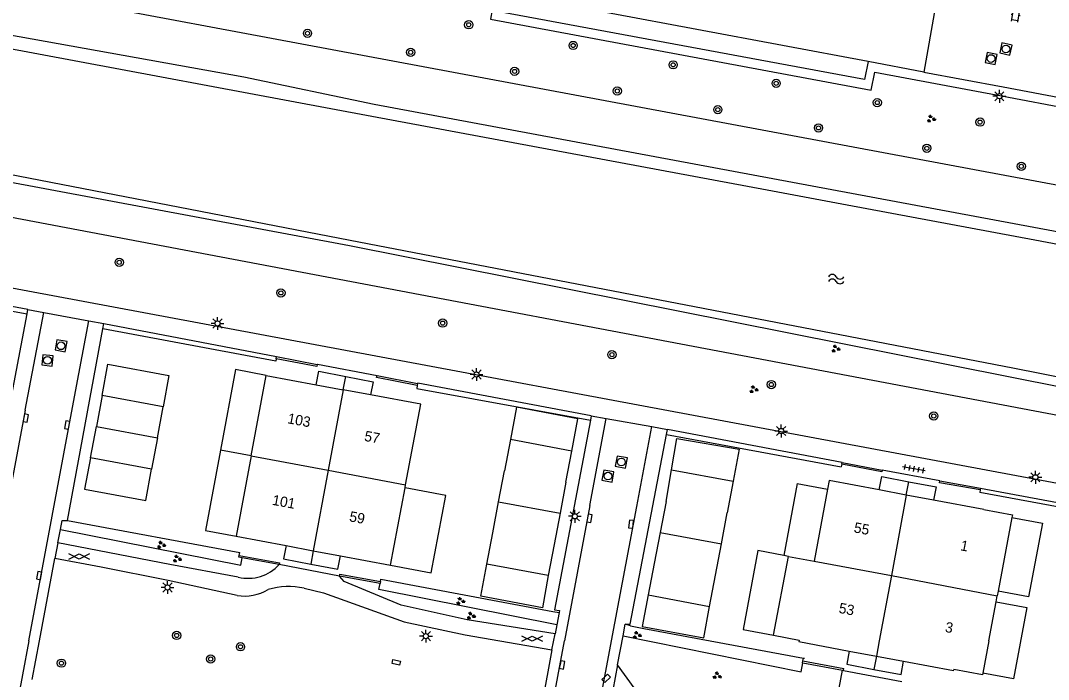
# Model space of a CAD drawing. Extents: x 124000 to 128010, y 398999 to 403000.
# Drawn here: x 126835.9 to 126935.6, y 399496.2 to 399560.1 of the extents above; entities that cross this region are included whole.
import ezdxf

# ---------------------------------------------------------------- set-up
doc = ezdxf.new("R2010")
doc.units = 0
for name, color, linetype in [('gg-afsc-hekwerk', 7, 'Continuous'), ('gg-afsc-muur', 7, 'Continuous'), ('gg-anno-huisnummerreeks BGT', 7, 'Continuous'), ('gg-bbg-bijgebouw', 7, 'Continuous'), ('gg-bbg-gedigitaliseerde bebouwing', 7, 'Continuous'), ('gg-bbg-hoofdgebouw', 7, 'Continuous'), ('gg-bbg-luifel en loopbrug', 7, 'Continuous'), ('gg-bbg-tussenscheiding', 7, 'Continuous'), ('gg-knt-BGT kruinlijn', 7, 'Continuous'), ('gg-knt-verharding', 7, 'Continuous'), ('gg-knt-verharding nz', 7, 'Continuous'), ('gg-kntw-beschoeiing', 7, 'Continuous'), ('gt-grn-groengrens', 7, 'Continuous'), ('gt-grn-vlakafsluiter', 7, 'Continuous'), ('gt-grn-weggrens', 7, 'Continuous'), ('gt-symb-boom', 7, 'Continuous'), ('gt-symb-gesloten verharding', 7, 'Continuous'), ('gt-symb-groenvak', 7, 'Continuous'), ('gt-symb-klinker verharding', 7, 'Continuous'), ('gt-symb-kolk', 7, 'Continuous'), ('gt-symb-kolk center center', 7, 'Continuous'), ('gt-symb-lichtmast', 7, 'Continuous'), ('gt-symb-rioolschacht', 7, 'Continuous'), ('gt-symb-tegel verharding', 7, 'Continuous'), ('gt-symb-watersymbool', 7, 'Continuous')]:
    doc.layers.add(name, color=color, linetype=linetype)

# ---------------------------------------------------------------- blocks, each defined once
blk = doc.blocks.new('gt0-GRVAK')
at = {"layer": 'gt-symb-groenvak'}
for p, q in [((-0.11, 0.189), (-0.228, 0.24)), ((-0.182, 0.153), (0.088, 0.153)), ((-0.091, 0.211), (-0.156, 0.322)), ((-0.047, 0.214), (-0.047, 0.393)), ((-0.004, 0.211), (0.061, 0.322)), ((0.015, 0.189), (0.133, 0.24)), ((0.262, -0.052), (0.197, 0.059)), ((0.305, -0.049), (0.305, 0.13)), ((0.349, -0.052), (0.414, 0.059)), ((-0.245, -0.228), (-0.363, -0.177)), ((-0.318, -0.264), (-0.047, -0.264)), ((-0.226, -0.206), (-0.291, -0.095)), ((-0.183, -0.203), (-0.183, -0.024)), ((-0.139, -0.206), (-0.074, -0.095)), ((-0.12, -0.228), (-0.002, -0.177)), ((0.243, -0.074), (0.125, -0.023)), ((0.17, -0.11), (0.441, -0.11)), ((0.368, -0.074), (0.486, -0.023))]:
    blk.add_line(p, q, dxfattribs=at)
blk = doc.blocks.new('gt0-GESVH1')
at = {"layer": 'gt-symb-gesloten verharding'}
for p, q in [((-0.992, -0.261), (0.008, 0.239)), ((0.008, -0.261), (-0.992, 0.239)), ((0.008, 0.239), (1.008, -0.261)), ((1.008, 0.239), (0.008, -0.261))]:
    blk.add_line(p, q, dxfattribs=at)
blk = doc.blocks.new('gt0-KOLK')
at = {"layer": 'gt-symb-kolk'}
blk.add_lwpolyline([(0, 0), (0.375, 0), (0.375, 0.4), (-0.375, 0.4), (-0.375, 0), (0, 0)], dxfattribs=at)
blk = doc.blocks.new('gt0-RS')
at = {"layer": 'gt-symb-rioolschacht'}
blk.add_lwpolyline([(-0.5, -0.5), (0.5, -0.5), (0.5, 0.5), (-0.5, 0.5)], close=True, dxfattribs=at)
blk.add_circle((0, 0), 0.375, dxfattribs=at)
blk = doc.blocks.new('gt0-KL1')
at = {"layer": 'gt-symb-klinker verharding'}
for p, q in [((-1.15, 0.3), (1.15, 0.3)), ((-1, -0.3), (-1, 0.3)), ((-0.5, 0.3), (-0.5, 0.45)), ((0, -0.3), (0, 0.3)), ((0.5, 0.3), (0.5, 0.45)), ((1, -0.3), (1, 0.3)), ((-1.15, -0.3), (1.15, -0.3)), ((-0.5, -0.45), (-0.5, -0.3)), ((0.5, -0.45), (0.5, -0.3))]:
    blk.add_line(p, q, dxfattribs=at)
blk = doc.blocks.new('gt0-LMAST')
at = {"layer": 'gt-symb-lichtmast'}
for p, q in [((-0.182, 0.173), (-0.447, 0.438)), ((-0.005, 0.246), (-0.005, 0.621)), ((0.172, 0.173), (0.437, 0.438)), ((-0.255, -0.004), (-0.63, -0.004)), ((-0.182, -0.181), (-0.447, -0.446)), ((-0.005, -0.254), (-0.005, -0.629)), ((0.437, -0.446), (0.172, -0.181)), ((0.245, -0.004), (0.62, -0.004))]:
    blk.add_line(p, q, dxfattribs=at)
blk.add_circle((-0.005, -0.004), 0.25, dxfattribs=at)
blk = doc.blocks.new('gt0-TEG1')
at = {"layer": 'gt-symb-tegel verharding'}
for p, q in [((-1.125, 0), (1.125, 0)), ((-0.9, -0.25), (-0.9, 0.25)), ((-0.45, -0.25), (-0.45, 0.25)), ((0, -0.25), (0, 0.25)), ((0.45, -0.25), (0.45, 0.25)), ((0.9, -0.25), (0.9, 0.25))]:
    blk.add_line(p, q, dxfattribs=at)
blk = doc.blocks.new('gt0-BOOM')
at = {"layer": 'gt-symb-boom'}
for radius in [0.4, 0.2]:
    blk.add_circle((0, 0), radius, dxfattribs=at)
blk = doc.blocks.new('gt0-WA')
at = {"layer": 'gt-symb-watersymbool'}
for centre, start, end in [((-0.323, 0.022), 28.07249, 151.92751), ((0.427, 0.422), 208.07248, 331.92751), ((-0.323, -0.428), 28.07249, 151.92751), ((0.427, -0.028), 208.07248, 331.92751)]:
    blk.add_arc(centre, 0.425, start, end, dxfattribs=at)
blk = doc.blocks.new('gt0-KOLKCC')
at = {"layer": 'gt-symb-kolk center center'}
blk.add_lwpolyline([(-0.375, 0.2), (0.375, 0.2), (0.375, -0.2), (-0.375, -0.2)], close=True, dxfattribs=at)

msp = doc.modelspace()

# ---------------------------------------------------------------- linework, layer by layer
at = {"layer": 'gg-afsc-hekwerk'}
for p, q in [((126819.677, 399534.791), (126836.523, 399531.69)), ((126860.637, 399527.113), (126843.878, 399530.249)), ((126874.301, 399524.469), (126891.148, 399521.38)), ((126898.516, 399520), (126915.46, 399516.872)), ((126945.627, 399511.253), (126928.899, 399514.374)), ((126840.463, 399511.656), (126857.142, 399508.54)), ((126870.828, 399505.979), (126887.508, 399502.845)), ((126895.043, 399501.44), (126896.325, 399501.201)), ((126896.325, 399501.201), (126902.763, 399500)), ((126902.763, 399500), (126911.804, 399498.313)), ((126911.804, 399498.313), (126911.887, 399498.298))]:
    msp.add_line(p, q, dxfattribs=at)
at = {"layer": 'gg-afsc-muur'}
for p, q in [((126860.68, 399527.344), (126860.721, 399527.557)), ((126860.721, 399527.557), (126864.668, 399526.784)), ((126870.461, 399525.723), (126874.392, 399524.944)), ((126874.392, 399524.944), (126874.354, 399524.753)), ((126915.51, 399517.106), (126915.543, 399517.279)), ((126915.543, 399517.279), (126919.446, 399516.553)), ((126925.035, 399515.49), (126928.977, 399514.798)), ((126928.977, 399514.798), (126928.945, 399514.623)), ((126860.982, 399507.388), (126857.391, 399508.039)), ((126870.746, 399505.54), (126866.82, 399506.267)), ((126870.781, 399505.728), (126870.746, 399505.54)), ((126911.719, 399497.864), (126911.756, 399498.06)), ((126911.719, 399497.864), (126911.754, 399497.857)), ((126911.754, 399497.857), (126915.574, 399497.13)), ((126911.756, 399498.06), (126915.708, 399497.308)), ((126915.574, 399497.13), (126915.67, 399497.112)), ((126915.67, 399497.112), (126915.708, 399497.308))]:
    msp.add_line(p, q, dxfattribs=at)
for points in [[(126864.668, 399526.784), (126864.629, 399526.582), (126860.68, 399527.344)], [(126874.354, 399524.753), (126870.422, 399525.521), (126870.461, 399525.723)], [(126919.446, 399516.553), (126919.414, 399516.379), (126915.51, 399517.106)], [(126928.945, 399514.623), (126925.006, 399515.325), (126925.035, 399515.49)], [(126857.391, 399508.039), (126857.062, 399508.099), (126857.093, 399508.275)], [(126857.093, 399508.275), (126861.014, 399507.563), (126860.982, 399507.388)], [(126866.82, 399506.267), (126866.854, 399506.454), (126870.781, 399505.728)]]:
    msp.add_lwpolyline(points, dxfattribs=at)
at = {"layer": 'gg-bbg-bijgebouw'}
for p, q in [((126843.805, 399523.78), (126843.244, 399520.76)), ((126849.723, 399522.68), (126843.805, 399523.78)), ((126849.162, 399519.661), (126849.723, 399522.68)), ((126842.683, 399517.742), (126843.244, 399520.76)), ((126849.162, 399519.661), (126848.602, 399516.643)), ((126883.388, 399519.523), (126882.813, 399516.485)), ((126889.347, 399518.395), (126883.388, 399519.523)), ((126888.763, 399515.368), (126889.347, 399518.395)), ((126848.602, 399516.643), (126842.683, 399517.742)), ((126882.249, 399513.48), (126882.813, 399516.485)), ((126898.48, 399513.507), (126899.011, 399516.574)), ((126899.011, 399516.574), (126904.98, 399515.455)), ((126888.763, 399515.368), (126888.199, 399512.363)), ((126904.98, 399515.455), (126904.407, 399512.396)), ((126881.681, 399510.453), (126882.249, 399513.48)), ((126898.48, 399513.507), (126897.913, 399510.509)), ((126888.199, 399512.363), (126887.63, 399509.336)), ((126903.845, 399509.398), (126904.407, 399512.396)), ((126881.114, 399507.434), (126881.681, 399510.453)), ((126897.913, 399510.509), (126897.341, 399507.484)), ((126887.63, 399509.336), (126887.063, 399506.317)), ((126903.277, 399506.371), (126903.845, 399509.398)), ((126887.063, 399506.317), (126881.114, 399507.434)), ((126897.341, 399507.484), (126896.744, 399504.441)), ((126902.705, 399503.323), (126903.277, 399506.371)), ((126896.744, 399504.441), (126902.705, 399503.323))]:
    msp.add_line(p, q, dxfattribs=at)
at = {"layer": 'gg-bbg-gedigitaliseerde bebouwing'}
for p, q in [((126914.136, 399514.69), (126912.828, 399507.714)), ((126908.908, 399500.536), (126910.34, 399508.18)), ((126910.34, 399508.18), (126912.828, 399507.714))]:
    msp.add_line(p, q, dxfattribs=at)
at = {"layer": 'gg-bbg-hoofdgebouw'}
for p, q in [((126858.246, 399517.94), (126859.7, 399525.731)), ((126859.7, 399525.731), (126864.551, 399524.825)), ((126864.551, 399524.825), (126867.19, 399524.332)), ((126869.829, 399523.839), (126867.19, 399524.332)), ((126858.246, 399517.94), (126856.787, 399510.125)), ((126873.176, 399514.825), (126873.231, 399515.118)), ((126871.776, 399507.327), (126873.176, 399514.825)), ((126921.775, 399514.126), (126919.137, 399514.62)), ((126924.413, 399513.631), (126921.775, 399514.126)), ((126929.284, 399512.718), (126924.413, 399513.631)), ((126932.02, 399511.957), (126930.679, 399504.802)), ((126856.787, 399510.125), (126861.635, 399509.22)), ((126861.635, 399509.22), (126864.274, 399508.727)), ((126864.274, 399508.727), (126866.913, 399508.235)), ((126866.913, 399508.235), (126871.776, 399507.327)), ((126930.485, 399503.769), (126930.597, 399504.367)), ((126930.679, 399504.802), (126930.597, 399504.367)), ((126929.778, 399500), (126930.485, 399503.769)), ((126908.908, 399500.536), (126911.395, 399500.07)), ((126929.778, 399500), (126929.188, 399496.851)), ((126916.237, 399499.001), (126918.875, 399498.506)), ((126918.875, 399498.506), (126921.513, 399498.012))]:
    msp.add_line(p, q, dxfattribs=at)
for points in [[(126873.231, 399515.118), (126874.69, 399522.932), (126869.829, 399523.839)], [(126919.137, 399514.62), (126914.293, 399515.528), (126914.136, 399514.69)], [(126929.284, 399512.718), (126932.065, 399512.196), (126932.02, 399511.957)], [(126911.395, 399500.07), (126911.366, 399499.914), (126916.237, 399499.001)], [(126921.513, 399498.012), (126926.356, 399497.104), (126926.374, 399497.202)], [(126929.188, 399496.851), (126929.156, 399496.681), (126926.374, 399497.202)]]:
    msp.add_lwpolyline(points, dxfattribs=at)
at = {"layer": 'gg-bbg-luifel en loopbrug'}
for p, q in [((126867.19, 399524.332), (126867.436, 399525.621)), ((126858.246, 399517.94), (126855.276, 399518.49)), ((126911.203, 399515.239), (126909.896, 399508.263)), ((126911.203, 399515.239), (126914.136, 399514.69)), ((126921.775, 399514.126), (126922.021, 399515.415)), ((126864.274, 399508.727), (126864.028, 399507.438)), ((126910.34, 399508.18), (126909.896, 399508.263)), ((126918.875, 399498.506), (126918.629, 399497.217))]:
    msp.add_line(p, q, dxfattribs=at)
for points in [[(126843.805, 399523.78), (126844.353, 399526.816), (126850.287, 399525.714), (126849.723, 399522.68)], [(126859.7, 399525.731), (126856.732, 399526.285), (126855.276, 399518.49)], [(126864.551, 399524.825), (126864.8, 399526.125), (126867.436, 399525.621)], [(126867.436, 399525.621), (126870.073, 399525.116), (126869.829, 399523.839)], [(126889.347, 399518.395), (126889.93, 399521.51), (126883.977, 399522.636), (126883.388, 399519.523)], [(126899.011, 399516.574), (126899.537, 399519.615), (126905.564, 399518.571), (126904.98, 399515.455)], [(126855.276, 399518.49), (126853.82, 399510.694), (126856.787, 399510.125)], [(126842.683, 399517.742), (126842.084, 399514.702), (126848.037, 399513.597), (126848.602, 399516.643)], [(126919.137, 399514.62), (126919.385, 399515.919), (126922.021, 399515.415)], [(126922.021, 399515.415), (126924.658, 399514.91), (126924.413, 399513.631)], [(126871.776, 399507.327), (126875.714, 399506.592), (126877.115, 399514.09), (126873.176, 399514.825)], [(126932.02, 399511.957), (126934.972, 399511.403), (126933.636, 399504.248), (126930.679, 399504.802)], [(126861.635, 399509.22), (126861.391, 399507.943), (126864.028, 399507.438)], [(126864.028, 399507.438), (126866.664, 399506.934), (126866.913, 399508.235)], [(126909.896, 399508.263), (126907.392, 399508.733), (126905.959, 399501.089), (126908.908, 399500.536)], [(126887.063, 399506.317), (126886.486, 399503.192), (126880.528, 399504.31), (126881.114, 399507.434)], [(126896.744, 399504.441), (126896.163, 399501.391), (126902.132, 399500.271), (126902.705, 399503.323)], [(126930.485, 399503.769), (126933.448, 399503.213), (126932.159, 399496.294), (126929.188, 399496.851)], [(126916.237, 399499.001), (126915.992, 399497.722), (126918.629, 399497.217)], [(126918.629, 399497.217), (126921.265, 399496.713), (126921.513, 399498.012)]]:
    msp.add_lwpolyline(points, dxfattribs=at)
at = {"layer": 'gg-bbg-tussenscheiding'}
for p, q in [((126867.19, 399524.332), (126865.732, 399516.53)), ((126843.244, 399520.76), (126849.162, 399519.661)), ((126858.246, 399517.94), (126865.732, 399516.53)), ((126865.732, 399516.53), (126864.274, 399508.727)), ((126865.732, 399516.53), (126873.231, 399515.118)), ((126921.775, 399514.126), (126920.325, 399506.316)), ((126882.249, 399513.48), (126888.199, 399512.363)), ((126897.913, 399510.509), (126903.845, 399509.398)), ((126912.828, 399507.714), (126920.325, 399506.316)), ((126920.325, 399506.316), (126919.152, 399500)), ((126920.325, 399506.316), (126930.597, 399504.367)), ((126919.152, 399500), (126918.875, 399498.506))]:
    msp.add_line(p, q, dxfattribs=at)
at = {"layer": 'gg-knt-BGT kruinlijn'}
msp.add_line((126950.486, 399519.162), (126787.178, 399550.094), dxfattribs=at)
msp.add_lwpolyline([(127000, 399532.278), (126705.207, 399587.393), (126693.827, 399589.723), (126689.664, 399589.521), (126684.973, 399588.254), (126682.307, 399588.784)], dxfattribs=at)
at = {"layer": 'gg-knt-verharding'}
for p, q in [((126924.581, 399561.351), (126923.471, 399555.13)), ((126923.471, 399555.13), (126918.085, 399556.15)), ((126930.987, 399552.82), (126938.671, 399551.367)), ((126949.326, 399512.823), (126785.932, 399543.354)), ((126836.606, 399532.128), (126819.765, 399535.264)), ((126836.523, 399531.69), (126836.606, 399532.128)), ((126836.606, 399532.128), (126838.15, 399531.839)), ((126832.985, 399513.037), (126836.523, 399531.69)), ((126836.357, 399522.348), (126838.15, 399531.839)), ((126838.15, 399531.839), (126842.515, 399531.021)), ((126841.231, 399524.168), (126842.515, 399531.021)), ((126842.515, 399531.021), (126843.97, 399530.748)), ((126840.463, 399511.656), (126843.878, 399530.249)), ((126843.878, 399530.249), (126843.97, 399530.748)), ((126843.97, 399530.748), (126860.721, 399527.557)), ((126836.701, 399500), (126841.231, 399524.168)), ((126836.357, 399522.348), (126832.134, 399500)), ((126891.094, 399513.122), (126892.678, 399521.554)), ((126891.23, 399521.814), (126891.148, 399521.38)), ((126891.23, 399521.814), (126892.678, 399521.554)), ((126892.678, 399521.554), (126897.093, 399520.762)), ((126895.637, 399513.013), (126897.093, 399520.762)), ((126897.093, 399520.762), (126898.61, 399520.49)), ((126898.516, 399520), (126898.61, 399520.49)), ((126915.543, 399517.279), (126898.61, 399520.49)), ((126925.035, 399515.49), (126919.446, 399516.553)), ((126928.977, 399514.798), (126945.706, 399511.678)), ((126891.094, 399513.122), (126888.629, 399500)), ((126893.192, 399500), (126895.637, 399513.013)), ((126839.521, 399509.5), (126839.765, 399510.796)), ((126839.521, 399509.5), (126839.235, 399507.98)), ((126837.734, 399500), (126839.235, 399507.98)), ((126866.82, 399506.267), (126860.982, 399507.388)), ((126888.103, 399502.734), (126887.877, 399501.533)), ((126887.877, 399501.533), (126887.717, 399500.681)), ((126894.314, 399500.472), (126894.529, 399501.613)), ((126887.421, 399499.108), (126887.717, 399500.681)), ((126893.786, 399497.665), (126894.314, 399500.472)), ((126837.024, 399496.231), (126837.734, 399500)), ((126887.421, 399499.108), (126885.003, 399486.26)), ((126915.67, 399497.112), (126921.355, 399496.045))]:
    msp.add_line(p, q, dxfattribs=at)
for points in [[(126880.451, 399562.322), (126881.783, 399562.074), (126881.457, 399560.282), (126918.367, 399553.381), (126918.721, 399555.139), (126930.987, 399552.82)], [(126918.085, 399556.15), (126917.707, 399554.417), (126882.486, 399560.957), (126882.764, 399562.777)], [(126864.668, 399526.784), (126864.674, 399526.813), (126870.461, 399525.723)], [(126891.23, 399521.814), (126874.4, 399524.982), (126874.392, 399524.944)], [(126891.148, 399521.38), (126887.669, 399502.99), (126888.139, 399502.924), (126888.103, 399502.734)], [(126894.529, 399501.613), (126895.007, 399501.62), (126898.516, 399520)], [(126839.765, 399510.796), (126839.928, 399511.659), (126840.463, 399511.656)], [(126857.007, 399506.151), (126850.354, 399507.385), (126839.521, 399509.5)], [(126856.897, 399504.372), (126850.208, 399505.848), (126843.708, 399507.138), (126839.235, 399507.98)], [(126887.717, 399500.681), (126879.191, 399502.035), (126872.804, 399503.45), (126867.28, 399505.746), (126866.82, 399506.267)], [(126863.389, 399505.087), (126865.283, 399504.644), (126873.077, 399501.831), (126878.992, 399500.58), (126887.421, 399499.108)], [(126836.701, 399500), (126832.374, 399476.902), (126829.81, 399462.975), (126827.176, 399449.222), (126826.994, 399448.111), (126821.981, 399421.546), (126819.42, 399407.629), (126812.345, 399369.809)], [(126859.41, 399345.721), (126859.812, 399345.958), (126860.245, 399348.522), (126874.185, 399422.789), (126876.299, 399434.381), (126882.625, 399467.842), (126888.629, 399500)], [(126864.05, 399344.335), (126867.497, 399362.533), (126872.812, 399391.194), (126881.431, 399436.976), (126887.006, 399467.005), (126893.192, 399500)], [(126916.433, 399491.479), (126895.389, 399495.424), (126893.786, 399497.665)], [(126916.433, 399491.479), (126917.108, 399495.067), (126915.248, 399495.399), (126915.574, 399497.13)]]:
    msp.add_lwpolyline(points, dxfattribs=at)
for centre, radius, start, end in [((126857.916, 399510.235), 4.184, 257.4542, 317.11756), ((126861.891, 399498.653), 6.606, 76.89794, 107.53502), ((126857.522, 399509.205), 4.873, 262.63248, 299.22345)]:
    msp.add_arc(centre, radius, start, end, dxfattribs=at)
at = {"layer": 'gg-knt-verharding nz'}
for p, q in [((126918.085, 399556.15), (126882.764, 399562.777)), ((126923.471, 399555.13), (126931.156, 399553.699)), ((126931.156, 399553.699), (126938.84, 399552.268))]:
    msp.add_line(p, q, dxfattribs=at)
at = {"layer": 'gg-kntw-beschoeiing'}
for p, q in [((126869.97, 399550.825), (126754.532, 399572.364)), ((126908.273, 399543.679), (126869.97, 399550.825)), ((126867.862, 399538.822), (126814.862, 399549.063)), ((126916.025, 399542.232), (126908.273, 399543.679)), ((126934.249, 399538.832), (126916.025, 399542.232)), ((126932.094, 399526.412), (126867.862, 399538.822)), ((126942.535, 399537.286), (126934.249, 399538.832)), ((126940.33, 399524.821), (126932.094, 399526.412))]:
    msp.add_line(p, q, dxfattribs=at)
at = {"layer": 'gt-grn-groengrens'}
for points in [[(127031.407, 399516.954), (127031.756, 399518.92), (127029.879, 399522.161), (127009.635, 399525.925), (127000, 399527.778), (126870.175, 399551.993), (126857.55, 399554.628), (126778.853, 399568.809), (126692.438, 399585.276), (126688.731, 399584.708)], [(126679.888, 399575.899), (126683.061, 399575.383), (126687.279, 399572.619), (126691.934, 399571.31), (126814.728, 399548.258), (126867.774, 399538.33), (127022.231, 399507.612), (127025.36, 399507.675), (127027.276, 399508.355), (127030.476, 399511.716), (127030.741, 399513.207)], [(126839.765, 399510.796), (126857.263, 399507.335), (126857.391, 399508.039)], [(126887.877, 399501.533), (126870.636, 399504.968), (126870.746, 399505.54)], [(126894.314, 399500.472), (126911.588, 399496.987), (126911.754, 399497.857)]]:
    msp.add_lwpolyline(points, dxfattribs=at)
at = {"layer": 'gt-grn-vlakafsluiter'}
for p, q in [((126860.68, 399527.344), (126860.637, 399527.113)), ((126874.354, 399524.753), (126874.301, 399524.469)), ((126915.51, 399517.106), (126915.46, 399516.872)), ((126928.945, 399514.623), (126928.899, 399514.374)), ((126857.093, 399508.275), (126857.142, 399508.54)), ((126870.781, 399505.728), (126870.828, 399505.979)), ((126887.508, 399502.845), (126888.103, 399502.734)), ((126895.043, 399501.44), (126894.529, 399501.613)), ((126911.756, 399498.06), (126911.804, 399498.313))]:
    msp.add_line(p, q, dxfattribs=at)
at = {"layer": 'gt-grn-weggrens'}
msp.add_line((126893.786, 399497.665), (126892.128, 399488.855), dxfattribs=at)

# ---------------------------------------------------------------- block references
at = {"layer": 'gt-symb-boom'}
for p in [(126879.351, 399559.723), (126863.719, 399558.896), (126889.475, 399557.717), (126873.723, 399557.053), (126899.167, 399555.842), (126883.796, 399555.202), (126909.154, 399554.044), (126893.75, 399553.301), (126918.958, 399552.177), (126903.498, 399551.498), (126913.262, 399549.722), (126928.927, 399550.285), (126923.766, 399547.749), (126932.93, 399545.999), (126845.463, 399536.687), (126861.137, 399533.723), (126876.819, 399530.797), (126893.231, 399527.741), (126908.688, 399524.84), (126924.438, 399521.795), (126851.029, 399500.513), (126857.222, 399499.413), (126839.862, 399497.824), (126854.323, 399498.224)]:
    msp.add_blockref('gt0-BOOM', p, dxfattribs=at)
at = {"layer": 'gt-symb-gesloten verharding'}
for p in [(126841.563, 399508.175), (126885.486, 399500.217)]:
    msp.add_blockref('gt0-GESVH1', p, dxfattribs=at)
at = {"layer": 'gt-symb-groenvak'}
for p in [(126924.169, 399550.597), (126914.916, 399528.3), (126906.964, 399524.363), (126849.522, 399509.283), (126851.063, 399507.935), (126878.535, 399503.843), (126879.56, 399502.406), (126895.651, 399500.539)]:
    msp.add_blockref('gt0-GRVAK', p, dxfattribs=at)
at = {"layer": 'gt-symb-groenvak', "rotation": -11.4223210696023}
msp.add_blockref('gt0-GRVAK', (126903.417, 399496.606), dxfattribs=at)
at = {"layer": 'gt-symb-klinker verharding', "rotation": 80.3869741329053}
msp.add_blockref('gt0-KL1', (126932.467, 399561.153), dxfattribs=at)
at = {"layer": 'gt-symb-kolk'}
for p, rotation in [((126836.21, 399521.632), -101.5907368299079), ((126840.612, 399520.888), 79.39794170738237), ((126890.86, 399511.906), -100.89418298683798), ((126895.294, 399511.274), 83.68511557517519), ((126837.893, 399506.282), 79.39794170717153), ((126888.198, 399497.698), -100.65836150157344), ((126892.541, 399496.508), -137.06710321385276)]:
    msp.add_blockref('gt0-KOLK', p, dxfattribs=dict(at, rotation=rotation))
at = {"layer": 'gt-symb-kolk center center', "rotation": 167.75714042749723}
msp.add_blockref('gt0-KOLKCC', (126872.325, 399497.894), dxfattribs=at)
at = {"layer": 'gt-symb-lichtmast'}
for p in [(126930.803, 399552.798), (126855.001, 399530.767), (126880.11, 399525.818), (126909.644, 399520.336), (126934.291, 399515.853), (126889.64, 399512.066), (126850.149, 399505.166), (126875.206, 399500.447)]:
    msp.add_blockref('gt0-LMAST', p, dxfattribs=at)
at = {"layer": 'gt-symb-rioolschacht'}
for p, rotation in [((126931.431, 399557.37), 77.52092819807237), ((126929.995, 399556.449), 79.21838326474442), ((126839.825, 399528.597), 79.74640197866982), ((126838.509, 399527.181), 173.2232171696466), ((126894.146, 399517.323), 79.28535610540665), ((126892.847, 399515.964), 79.28535610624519)]:
    msp.add_blockref('gt0-RS', p, dxfattribs=dict(at, rotation=rotation))
at = {"layer": 'gt-symb-tegel verharding', "rotation": 169.51061018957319}
msp.add_blockref('gt0-TEG1', (126922.497, 399516.669), dxfattribs=at)
at = {"layer": 'gt-symb-watersymbool'}
msp.add_blockref('gt0-WA', (126914.921, 399535.065), dxfattribs=at)

# ---------------------------------------------------------------- texts
at = {"layer": 'gg-anno-huisnummerreeks BGT'}
for s, rotation, p in [('103', 349.5, (126861.718, 399521.094)), ('57', 349.4, (126869.169, 399519.39)), ('101', 349.4, (126860.242, 399513.189)), ('59', 349.4, (126867.712, 399511.591)), ('55', 349.4, (126916.633, 399510.518)), ('1', 349.4, (126926.959, 399508.777)), ('53', 349.4, (126915.169, 399502.711)), ('3', 349.4, (126925.475, 399500.864))]:
    msp.add_text(s, height=1, rotation=rotation, dxfattribs=at).set_placement(p)

doc.saveas('drawing.dxf')
